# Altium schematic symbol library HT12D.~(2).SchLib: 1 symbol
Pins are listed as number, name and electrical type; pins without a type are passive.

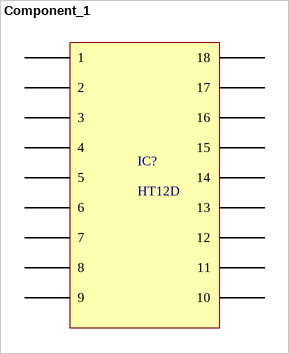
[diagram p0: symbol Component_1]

## Component_1
designator IC?, comment HT12D
footprint HT12D
pins: 1, 2, 3, 4, 5, 6, 7, 8, 9, 10, 11, 12, 13, 14, 15, 16, 17, 18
